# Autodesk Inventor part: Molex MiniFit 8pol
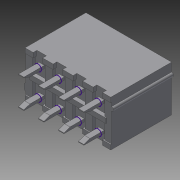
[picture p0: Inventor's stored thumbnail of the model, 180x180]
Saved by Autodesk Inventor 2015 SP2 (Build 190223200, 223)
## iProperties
Created: 2015-08
Part Number: Molex MiniFit 8pol
Material: Allgemein
Document SubType Name: Modeling
Designer: ryll
Density: 1 g/cm^3
Appearance: Vorgabe
Author: me
Title: 039281083.igs
Organization: Unknown
Description: PTC IGES file: 039281083.igs
Creation Date: 2015-05-15
Sending System: Creo Parametric by Parametric Technology Corporation
Preprocessor: 2011490
Minimum Resolution: 0.001
Sending System Product ID: 039281083
Receiving System Product ID: 039281083
Sent Units: Millimeter
Translation Standard: USPRO/IPO100 IGES 5.2
Model Creation Time: 2015-05-15
Author: ryll
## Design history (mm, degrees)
node "0392810831"
  sketch "3D-Skizze1"
node "MSBR"
node "Basis1"
